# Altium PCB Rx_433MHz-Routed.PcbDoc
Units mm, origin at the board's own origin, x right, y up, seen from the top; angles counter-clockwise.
Board outline 100 x 50 mm, 4 copper layers (SIGNAL_1, SIGNAL_2, SIGNAL_3, SIGNAL_4), stack 1.58 mm thick; 51 components, 60 nets, 198 pads, 218 vias.
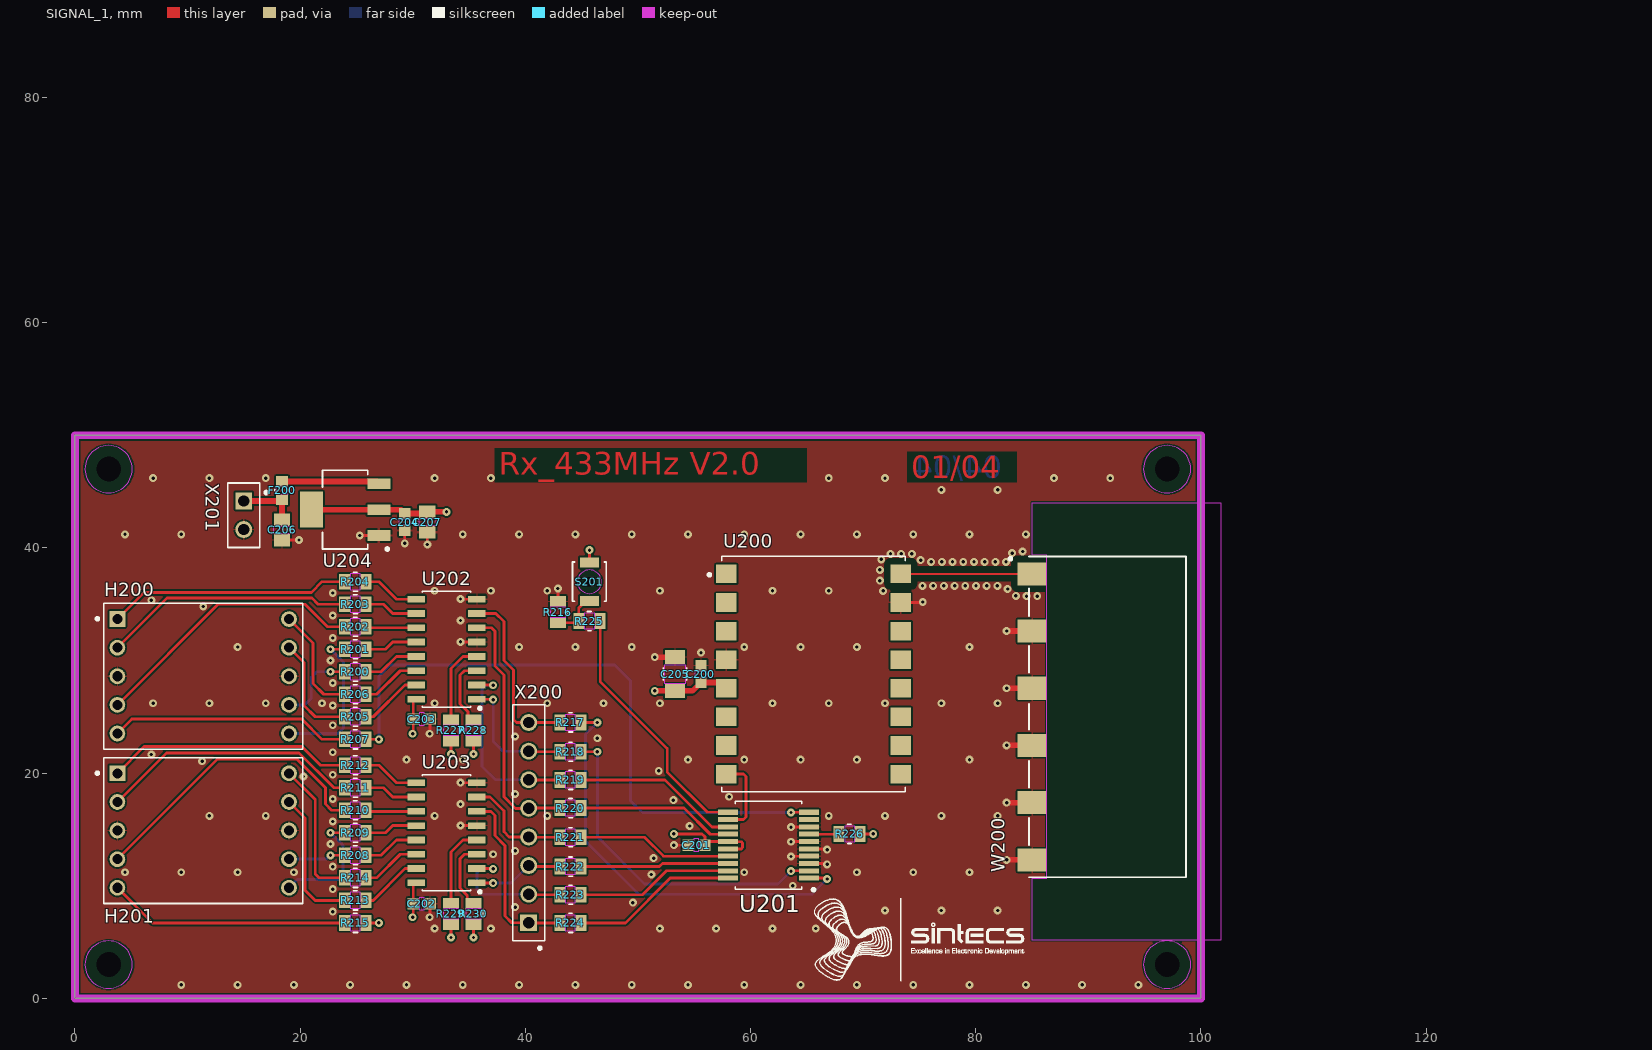
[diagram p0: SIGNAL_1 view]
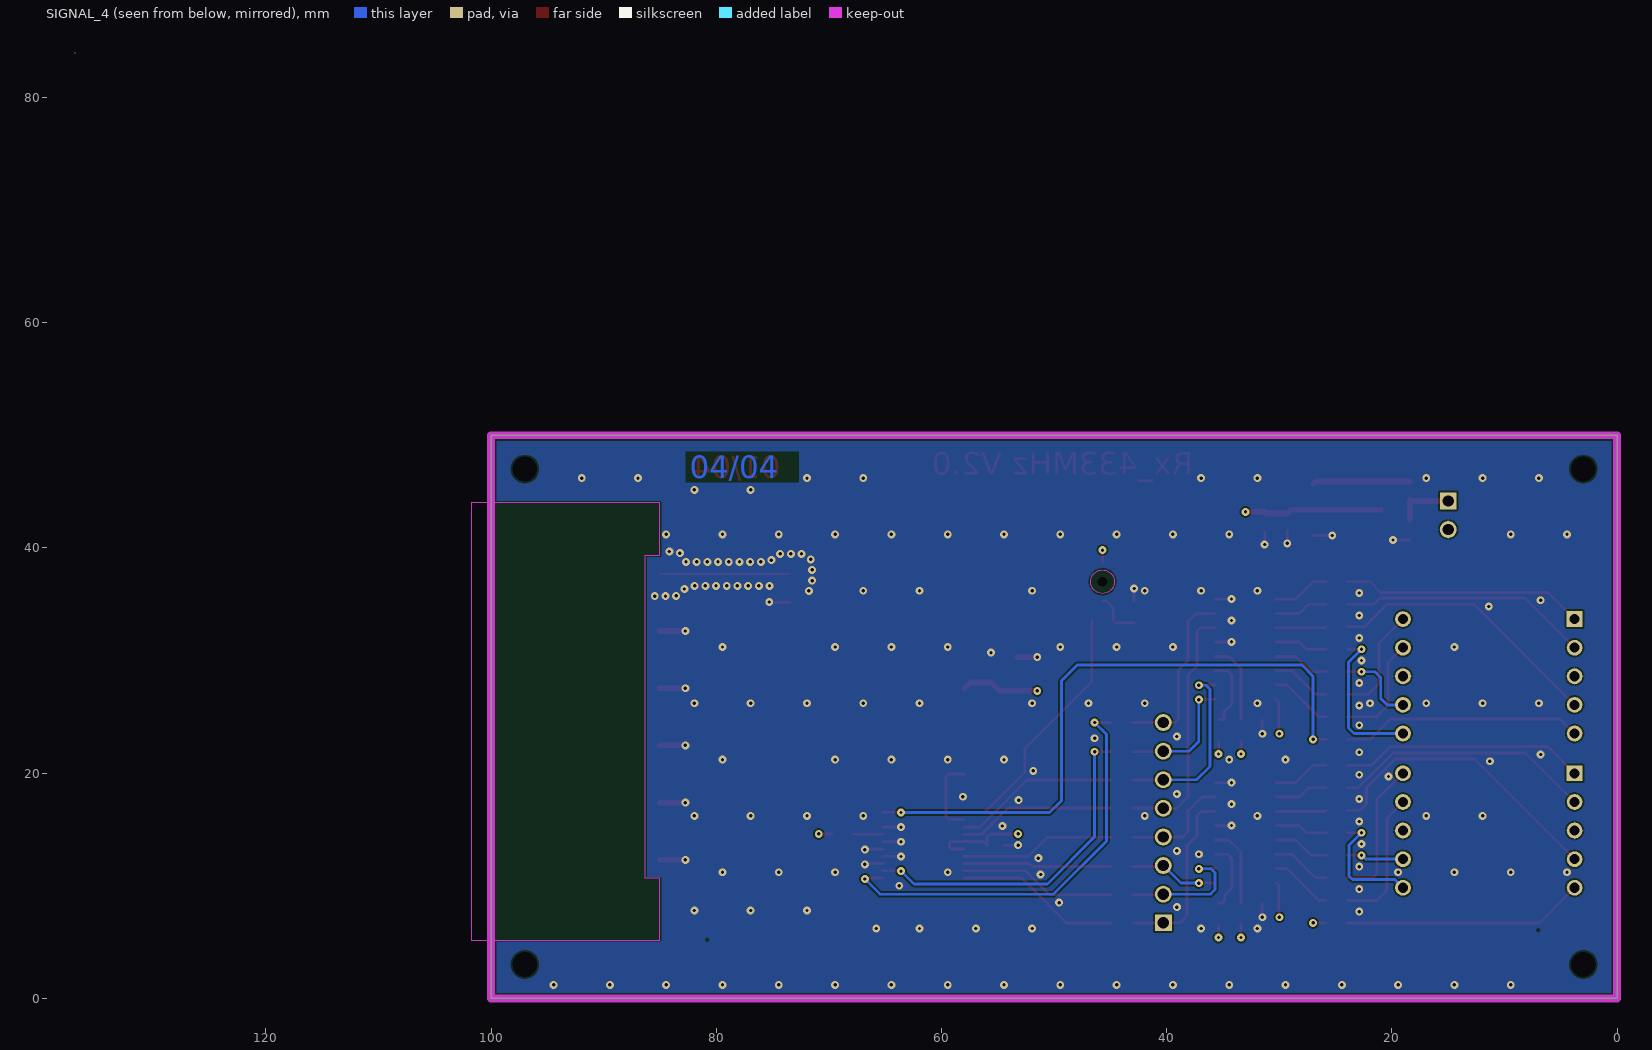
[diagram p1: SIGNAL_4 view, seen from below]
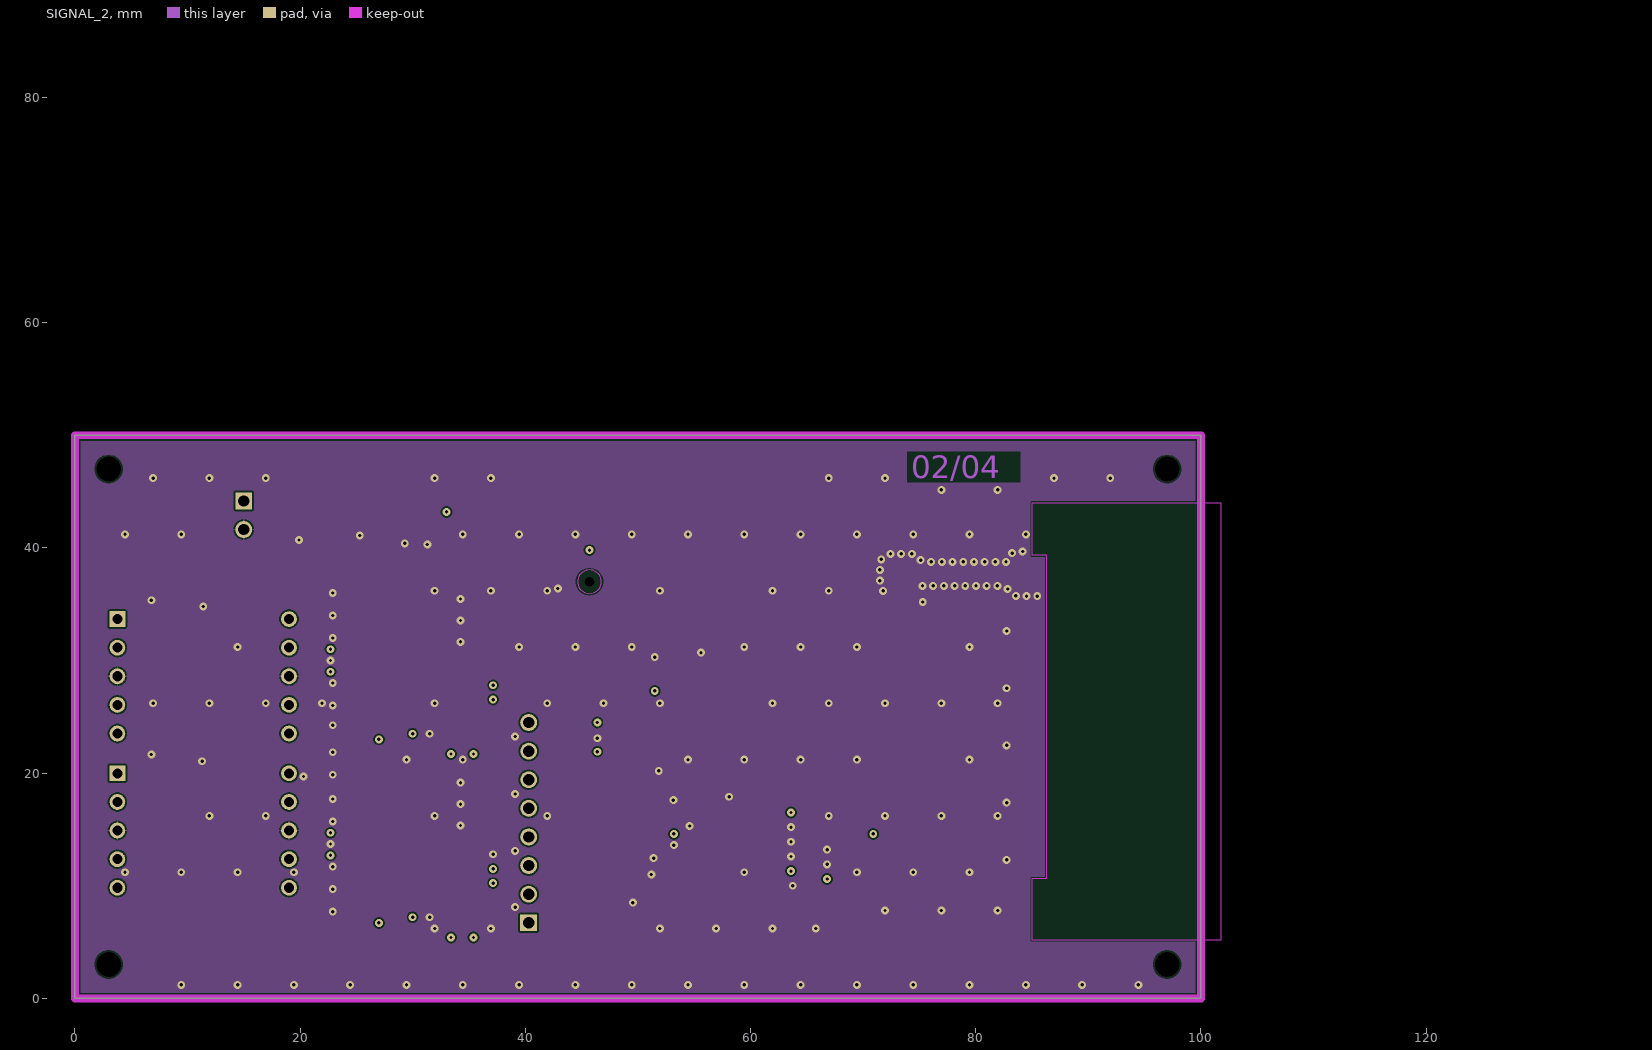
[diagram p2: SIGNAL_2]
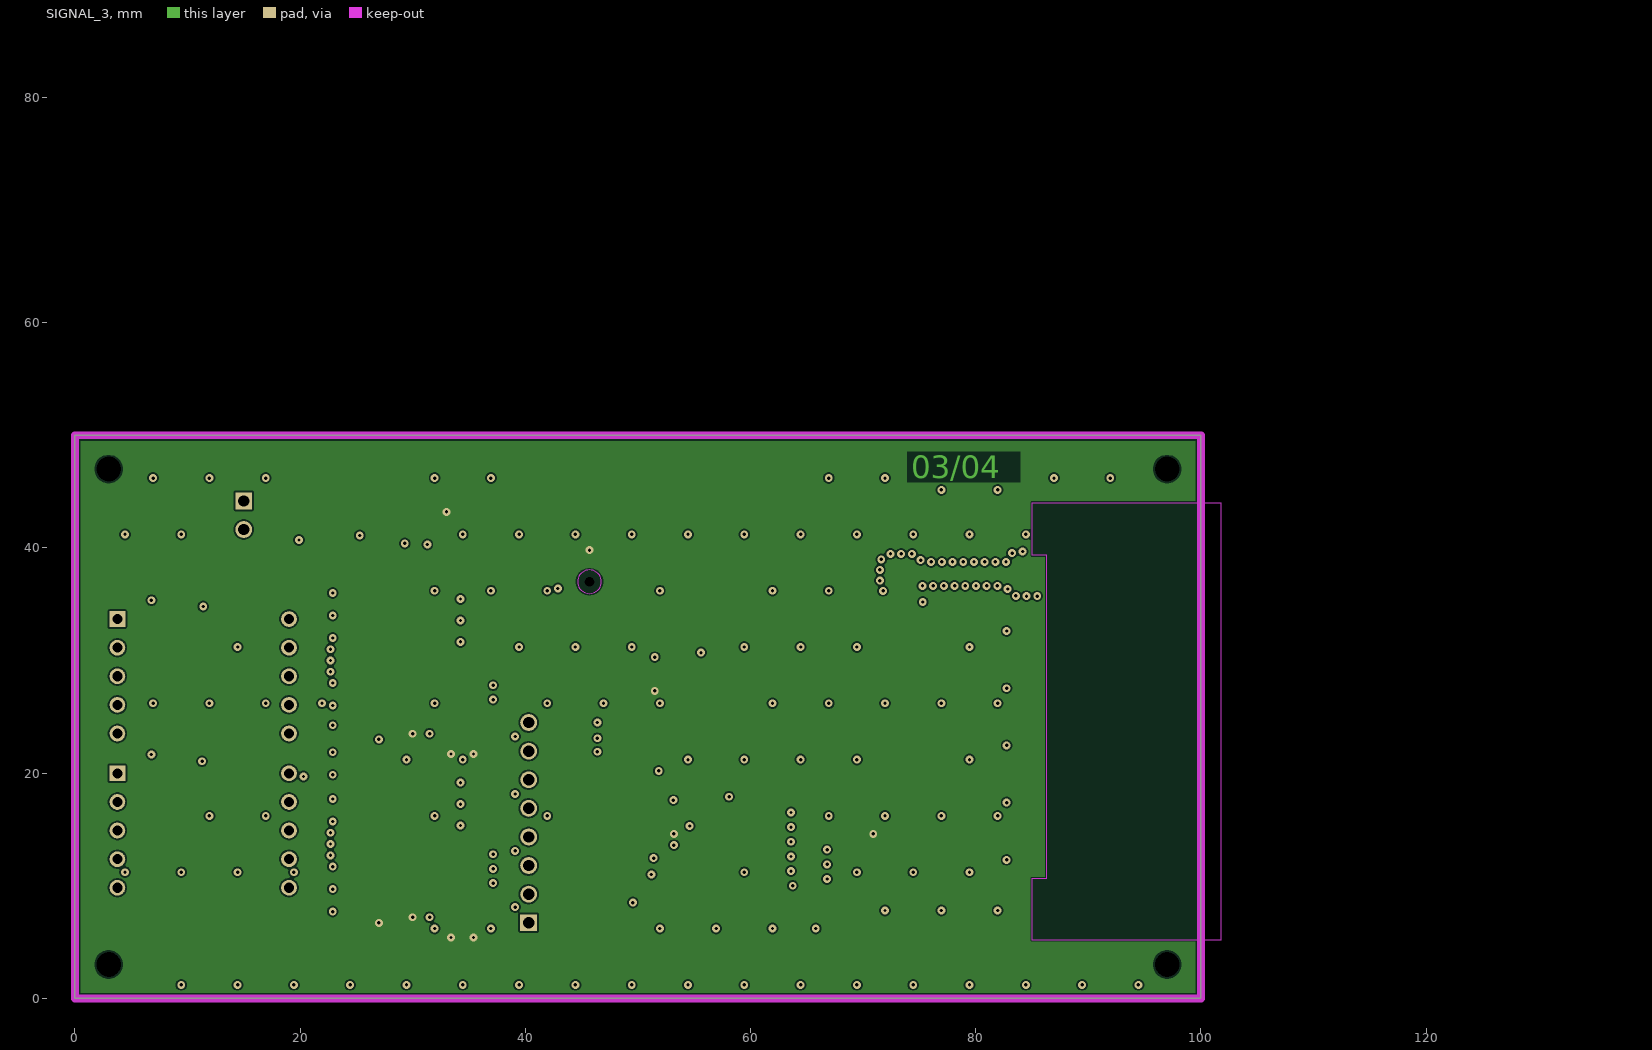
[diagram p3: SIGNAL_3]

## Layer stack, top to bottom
DIELECTRIC_1: solder mask 0.01, Dk 1
SIGNAL_1: signal copper 0.035
DIELECTRIC_3: prepreg 0.12, Dk 4.7
SIGNAL_2: signal copper 0.035
DIELECTRIC_5: prepreg 1.2, Dk 4.7
SIGNAL_3: signal copper 0.035
DIELECTRIC_7: prepreg 0.12, Dk 4.7
SIGNAL_4: signal copper 0.035
DIELECTRIC_9: solder mask 0.01, Dk 1

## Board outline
0,0 0,50 100,50 100,0

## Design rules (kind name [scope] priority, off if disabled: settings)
Clearance Clearance_50R [InNetClass('50R')] p1: gap=0.6 ignorepadtopadclearanceinfootprint=FALSE except(0.2: SMDPad-SMDPad)
Clearance [All] p2: gap=0.15 ignorepadtopadclearanceinfootprint=FALSE
ComponentClearance [All] p1: gap=0.1 collisioncheckmode=3 verticalgap=0.254 showdistances=FALSE
DiffPairsRouting [All] p1: maxlimit=0.254 minlimit=0.254 mostfreqgap=0.254 toplayer_minwidth=0.15 toplayer_maxwidth=0.3 toplayer_prefwidth=0.15 midlayer1_minwidth=0.15 midlayer1_maxwidth=0.3 midlayer1_prefwidth=0.15 midlayer2_minwidth=0.15 midlayer2_maxwidth=0.3 midlayer2_prefwidth=0.15 bottomlayer_minwidth=0.15 bottomlayer_maxwidth=0.3 bottomlayer_prefwidth=0.15 maxuncoupledlength=12.7
MinimumSolderMaskSliver [All] p1: minsoldermaskwidth=0.1
PolygonConnect [All] p1: thpad.connectstyle=Relief thpad.reliefconductorwidth=0.15 thpad.reliefentries=4 thpad.polygonreliefangle="90 Angle" thpad.airgapwidth=0.15 smdpad.connectstyle=Relief smdpad.reliefconductorwidth=0.15 smdpad.reliefentries=4 smdpad.polygonreliefangle="90 Angle" smdpad.airgapwidth=0.15 via.connectstyle=Direct via.reliefconductorwidth=0.127 via.reliefentries=2 via.polygonreliefangle="90 Angle" via.airgapwidth=0.152
RoutingVias [All] p1: holewidth=0.3 width=0.7 viastyle="Through Hole" minholewidth=0.3 minwidth=0.7 maxholewidth=0.3 maxwidth=0.7
SilkToSilkClearance [All] p1: silktosilkclearance=0.1
SolderMaskExpansion SolderMaskExpansion_Via [IsVia] p1: expansion=0.075 istentingtop=FALSE soldermaskfromhole=TRUE
SolderMaskExpansion [All] p2: expansion=0.1 istentingtop=FALSE
SupplyNets "Schematic Supply Nets_1" [InNet('3V3_RX')] p1: voltage=0.000
SupplyNets "Schematic Supply Nets" [InNet('GND_RX')] p2: voltage=0.000
UnRoutedNet [All] p1: checkbadconnections=TRUE
Width "Width for 50E_SE" [InNetClass('50R')] p1: maxlimit=0.2 minlimit=0.185 preferedwidth=0.2 toplayer_minwidth=0.2 bottomlayer_minwidth=0.2 impedanceprofiledriven=TRUE impedanceprofileid={877E34D1-77DC-4DEE-A0FB-207FE4FBDA97} impedanceprofilevalue=50.000000 minimp=50.000000 maximp=50.000000 favimp=50.000000
Width [All] p2: maxlimit=1 minlimit=0.15 preferedwidth=0.2
25 further rules are at their usual default settings.

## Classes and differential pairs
net class 50R: RF_RX
polygon class "\"(Inherited)\"": GND_RX_L02_P002

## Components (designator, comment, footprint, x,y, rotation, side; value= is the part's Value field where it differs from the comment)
C200 "C_0603_1608X90_GENERIC" CAPC1608X90N_0603_GENERIC 55.6,28.8 r90 top value=100nF
C201 "C_0603_1608X90_GENERIC" CAPC1608X90N_0603_GENERIC 55.2,13.6 r180 top value=100nF
C202 "C_0603_1608X90_GENERIC" CAPC1608X90N_0603_GENERIC 30.8,8.4 r0 top value=100nF
C203 "C_0603_1608X90_GENERIC" CAPC1608X90N_0603_GENERIC 30.8,24.8 r0 top value=100nF
C204 "C_0603_1608X90_GENERIC" CAPC1608X90N_0603_GENERIC 29.3,42.3 r270 top value=100nF
C205 "C_1206_3216X190_GENERIC" CAPC3216X190N_1206_GENERIC 53.3,28.8 r90 top value=10uF
C206 "08051C104KAZ2A" CAPC2013X140N_AVX 18.398,41.6 r270 top value=10uF
C207 "08051C104KAZ2A" CAPC2013X140N_AVX 31.3,42.3 r270 top value=10uF
F200 "0467XXXX" RESC1608X60N_0603_GENERIC 18.4,45.1 r90 top value=500mA
H200 "HDSP-5XXX" BROADCOM_HDSP-5XXX 11.4,28.6 r0 top
H201 "HDSP-5XXX" BROADCOM_HDSP-5XXX 11.4,14.9 r0 top
R200 "R_0805_2012X60_GENERIC" RESC2012X60N_0805_GENERIC 24.9,29.001 r180 top value=120R
R201 "R_0805_2012X60_GENERIC" RESC2012X60N_0805_GENERIC 24.9,31.001 r180 top value=120R
R202 "R_0805_2012X60_GENERIC" RESC2012X60N_0805_GENERIC 24.9,33.001 r180 top value=120R
R203 "R_0805_2012X60_GENERIC" RESC2012X60N_0805_GENERIC 24.9,35.001 r180 top value=120R
R204 "R_0805_2012X60_GENERIC" RESC2012X60N_0805_GENERIC 24.9,37.002 r180 top value=120R
R205 "R_0805_2012X60_GENERIC" RESC2012X60N_0805_GENERIC 24.9,25 r180 top value=120R
R206 "R_0805_2012X60_GENERIC" RESC2012X60N_0805_GENERIC 24.9,27 r180 top value=120R
R207 "R_0805_2012X60_GENERIC" RESC2012X60N_0805_GENERIC 24.9,23 r180 top value=120R
R208 "R_0805_2012X60_GENERIC" RESC2012X60N_0805_GENERIC 24.9,12.7 r180 top value=120R
R209 "R_0805_2012X60_GENERIC" RESC2012X60N_0805_GENERIC 24.9,14.7 r180 top value=120R
R210 "R_0805_2012X60_GENERIC" RESC2012X60N_0805_GENERIC 24.9,16.701 r180 top value=120R
R211 "R_0805_2012X60_GENERIC" RESC2012X60N_0805_GENERIC 24.9,18.701 r180 top value=120R
R212 "R_0805_2012X60_GENERIC" RESC2012X60N_0805_GENERIC 24.9,20.701 r180 top value=120R
R213 "R_0805_2012X60_GENERIC" RESC2012X60N_0805_GENERIC 24.9,8.7 r180 top value=120R
R214 "R_0805_2012X60_GENERIC" RESC2012X60N_0805_GENERIC 24.9,10.7 r180 top value=120R
R215 "R_0805_2012X60_GENERIC" RESC2012X60N_0805_GENERIC 24.9,6.7 r180 top value=120R
R216 "R_0805_2012X60_GENERIC" RESC2012X60N_0805_GENERIC 42.9,34.3 r270 top value=100K
R217 "R_0805_2012X60_GENERIC" RESC2012X60N_0805_GENERIC 44,24.5 r180 top value=1K
R218 "R_0805_2012X60_GENERIC" RESC2012X60N_0805_GENERIC 44,21.9 r180 top value=1K
R219 "R_0805_2012X60_GENERIC" RESC2012X60N_0805_GENERIC 44,19.4 r180 top value=1K
R220 "R_0805_2012X60_GENERIC" RESC2012X60N_0805_GENERIC 44,16.9 r180 top value=1K
R221 "R_0805_2012X60_GENERIC" RESC2012X60N_0805_GENERIC 44,14.3 r180 top value=1K
R222 "R_0805_2012X60_GENERIC" RESC2012X60N_0805_GENERIC 44,11.7 r180 top value=1K
R223 "R_0805_2012X60_GENERIC" RESC2012X60N_0805_GENERIC 44,9.2 r180 top value=1K
R224 "R_0805_2012X60_GENERIC" RESC2012X60N_0805_GENERIC 44,6.7 r180 top value=1K
R225 "R_0805_2012X60_GENERIC" RESC2012X60N_0805_GENERIC 45.7,33.5 r0 top value=1K
R226 "R_0805_2012X60_GENERIC" RESC2012X60N_0805_GENERIC 68.8,14.6 r0 top value=100K
R227 "R_0805_2012X60_GENERIC" RESC2012X60N_0805_GENERIC 33.4,23.8 r270 top value=100K
R228 "R_0805_2012X60_GENERIC" RESC2012X60N_0805_GENERIC 35.4,23.8 r270 top value=100K
R229 "R_0805_2012X60_GENERIC" RESC2012X60N_0805_GENERIC 33.4,7.5 r270 top value=100K
R230 "R_0805_2012X60_GENERIC" RESC2012X60N_0805_GENERIC 35.4,7.5 r270 top value=100K
S201 "B3U_1000P_B" OMRON_B3U_1000P_B 45.7,37 r270 top
U200 "RXM-433-LR" LINX_RXM-433-LR 65.6,28.8 r0 top
U201 "LICAL-DEC-MS001" SOP65P780X200-20N 61.6,13.6 r180 top
U202 "CD74HC4511M" SOIC127P600X175-16N 33,31 r180 top
U203 "CD74HC4511M" SOIC127P600X175-16N 33,14.7 r180 top
U204 "LM1117MPX" SOT230P700X180-4N 25.498,43.4 r180 top
W200 "ANT-433-SP" LINX_ANT-433-SP 85,25 r270 top
X200 "M20_9770842" HARWIN_M20_9770842 40.3,15.6 r90 top
X201 "M20_9770242" HARWIN_M20_9770242 15,42.9 r270 top

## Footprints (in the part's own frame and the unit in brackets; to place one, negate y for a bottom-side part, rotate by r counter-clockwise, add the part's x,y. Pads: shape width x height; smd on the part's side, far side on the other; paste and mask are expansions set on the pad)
BROADCOM_HDSP-5XXX [mm]
  rrect1% 1.4x1.4 hole 0.9 paste-2539.97 mask-0.713: 1(-7.62,5.08)
  round 1.4 hole 0.9 paste-2539.97 mask-0.713: 2(-7.62,2.54) 3(-7.62,0) 4(-7.62,-2.54) 5(-7.62,-5.08) 6(7.62,-5.08) 7(7.62,-2.54) 8(7.62,0) 9(7.62,2.54) 10(7.62,5.08)
  silkscreen extent -9.53,-6.47 8.83,6.48, body extent -8.92,-6.57 8.93,6.58, height 8.25
CAPC1608X90N_0603_GENERIC [mm]
  rrect1% 1x1 smd paste-2539.97 mask-0.513: 1(-0.75,0) 2(0.75,0)
  SIGNAL_1 keep-out region: -0.22,-0.55 0.22,-0.55 0.22,0.55 -0.22,0.55
  body extent -1.5,-0.75 1.5,0.75, height 0.9
CAPC2013X140N_AVX [mm]
  rrect1% 1.15x1.45 smd paste-2539.97 mask-0.738: 1(-0.9,0) 2(0.9,0)
  SIGNAL_1 keep-out region: -0.28,-0.78 0.28,-0.78 0.28,0.78 -0.28,0.78
  body extent -1.73,-1.05 1.73,1.05, height 1.4
CAPC3216X190N_1206_GENERIC [mm]
  rrect1% 1.25x1.8 smd paste-2539.97 mask-0.913: 1(-1.5,0) 2(1.5,0)
  SIGNAL_1 keep-out region: -0.8,-0.95 0.8,-0.95 0.8,0.95 -0.8,0.95
  silkscreen extent -0.55,-1.05 0.55,1.05, body extent -2.4,-1.15 2.4,1.15, height 1.9
HARWIN_M20_9770242 [mm]
  rrect1% 1.5x1.5 hole 1 paste-2539.97 mask-0.763: 1(-1.27,0)
  round 1.5 hole 1 paste-2539.97 mask-0.763: 2(1.27,0)
  silkscreen extent -2.87,-1.42 2.86,2.12, body extent -2.97,-1.52 2.96,1.52, height 8.38
HARWIN_M20_9770842 [mm]
  rrect1% 1.5x1.5 hole 1 paste-2539.97 mask-0.763: 1(-8.89,0)
  round 1.5 hole 1 paste-2539.97 mask-0.763: 2(-6.35,0) 3(-3.81,0) 4(-1.27,0) 5(1.27,0) 6(3.81,0) 7(6.35,0) 8(8.89,0)
  silkscreen extent -11.26,-1.42 10.48,1.42, body extent -10.59,-1.52 10.59,1.52, height 8.34
LINX_ANT-433-SP [mm]
  rrect1% 2.05x2.55 smd paste-2539.97 mask-1.288: 1(-12.7,0) 2(-7.62,0) 3(-2.54,0) 4(2.54,0) 5(7.62,0) 6(12.7,0)
  SIGNAL_1 keep-out region: 14.35,0 14.35,1.3 -14.35,1.3 -14.35,0 -19.03,0 -19.03,16.78 19.83,16.78 19.83,0
  SIGNAL_2 keep-out region: 14.35,0 14.35,1.3 -14.35,1.3 -14.35,0 -19.03,0 -19.03,16.78 19.83,16.78 19.83,0
  SIGNAL_3 keep-out region: 14.35,0 14.35,1.3 -14.35,1.3 -14.35,0 -19.03,0 -19.03,16.78 19.83,16.78 19.83,0
  SIGNAL_4 keep-out region: 14.35,0 14.35,1.3 -14.35,1.3 -14.35,0 -19.03,0 -19.03,16.78 19.83,16.78 19.83,0
  silkscreen extent -14.24,-2.04 14.24,13.67, body extent -14.34,-1.55 14.34,13.77, height 1.5
LINX_RXM-433-LR [mm]
  rrect1% 1.8x1.65 smd paste-2539.97 mask-0.913: 1(-7.747,8.89) 2(-7.747,6.35) 3(-7.747,3.81) 4(-7.747,1.27) 5(-7.747,-1.27) 6(-7.747,-3.81) 7(-7.747,-6.35) 8(-7.747,-8.89) 9(7.747,-8.89) 10(7.747,-6.35) 11(7.747,-3.81) 12(7.747,-1.27) 13(7.747,1.27) 14(7.747,3.81) 15(7.747,6.35) 16(7.747,8.89)
  silkscreen extent -9.38,-10.45 8.15,10.45, body extent -8.9,-10.65 8.9,10.65, height 3.12
OMRON_B3U_1000P_B [mm]
  rrect1% 0.9x1.7 smd paste-2539.97 mask-0.863: 1(-1.7,0) 2(1.7,0)
  round 0 hole 0.85 unplated paste-2539.97 mask+0.925: ""(0,0)
  SIGNAL_1 keep-out region: 1.05,0 0.97,0.402 0.742,0.742 0.402,0.97 0,1.05 0,1.05 -0.402,0.97 -0.742,0.742 -0.97,0.402 -1.05,0 -1.05,0 -0.97,-0.402 -0.742,-0.742 -0.402,-0.97 0,-1.05 0,-1.05 0.402,-0.97 0.742,-0.742 0.97,-0.402 1.05,0
  SIGNAL_2 keep-out region: 1.05,0 0.97,0.402 0.742,0.742 0.402,0.97 0,1.05 0,1.05 -0.402,0.97 -0.742,0.742 -0.97,0.402 -1.05,0 -1.05,0 -0.97,-0.402 -0.742,-0.742 -0.402,-0.97 0,-1.05 0,-1.05 0.402,-0.97 0.742,-0.742 0.97,-0.402 1.05,0
  SIGNAL_3 keep-out region: 1.05,0 0.97,0.402 0.742,0.742 0.402,0.97 0,1.05 0,1.05 -0.402,0.97 -0.742,0.742 -0.97,0.402 -1.05,0 -1.05,0 -0.97,-0.402 -0.742,-0.742 -0.402,-0.97 0,-1.05 0,-1.05 0.402,-0.97 0.742,-0.742 0.97,-0.402 1.05,0
  SIGNAL_4 keep-out region: 1.05,0 0.97,0.402 0.742,0.742 0.402,0.97 0,1.05 0,1.05 -0.402,0.97 -0.742,0.742 -0.97,0.402 -1.05,0 -1.05,0 -0.97,-0.402 -0.742,-0.742 -0.402,-0.97 0,-1.05 0,-1.05 0.402,-0.97 0.742,-0.742 0.97,-0.402 1.05,0
  silkscreen extent -1.75,-1.5 1.75,1.5, body extent -2.4,-1.6 2.4,1.6, height 1.75
RESC1608X60N_0603_GENERIC [mm]
  rrect1% 0.95x1.05 smd paste-2539.97 mask-0.538: 1(-0.8,0) 2(0.8,0)
  SIGNAL_1 keep-out region: -0.3,-0.55 0.3,-0.55 0.3,0.55 -0.3,0.55
  silkscreen extent -0.08,-0.65 0.08,0.65, body extent -1.55,-0.8 1.55,0.8, height 0.6
RESC2012X60N_0805_GENERIC [mm]
  rrect1% 0.95x1.4 smd paste-2539.97 mask-0.713: 1(-0.95,0) 2(0.95,0)
  SIGNAL_1 keep-out region: -0.45,-0.7 0.45,-0.7 0.45,0.7 -0.45,0.7
  silkscreen extent -0.2,-0.85 0.15,0.85, body extent -1.7,-0.95 1.7,0.95, height 0.6
SOIC127P600X175-16N [mm]
  rrect1% 1.55x0.6 smd paste-2539.97 mask-0.788: 1(-2.7,4.445) 2(-2.7,3.175) 3(-2.7,1.905) 4(-2.7,0.635) 5(-2.7,-0.635) 6(-2.7,-1.905) 7(-2.7,-3.175) 8(-2.7,-4.445) 9(2.7,-4.445) 10(2.7,-3.175) 11(2.7,-1.905) 12(2.7,-0.635) 13(2.7,0.635) 14(2.7,1.905) 15(2.7,3.175) 16(2.7,4.445)
  silkscreen extent -3.1,-5.16 2.15,5.38, body extent -3.73,-5.25 3.73,5.25, height 1.75
SOP65P780X200-20N [mm]
  rrect1% 1.75x0.45 smd paste-2539.97 mask-0.888: 1(-3.6,2.925) 2(-3.6,2.275) 3(-3.6,1.625) 4(-3.6,0.975) 5(-3.6,0.325) 6(-3.6,-0.325) 7(-3.6,-0.975) 8(-3.6,-1.625) 9(-3.6,-2.275) 10(-3.6,-2.925) 11(3.6,-2.925) 12(3.6,-2.275) 13(3.6,-1.625) 14(3.6,-0.975) 15(3.6,-0.325) 16(3.6,0.325) 17(3.6,0.975) 18(3.6,1.625) 19(3.6,2.275) 20(3.6,2.925)
  silkscreen extent -4.12,-3.9 2.95,4.08, body extent -4.75,-4 4.75,4, height 2
SOT230P700X180-4N [mm]
  rrect1% 2.05x0.95 smd paste-2539.97 mask-1.038: 1(-1.5,2.3) 2(-1.5,0) 3(-1.5,-2.3)
  rrect1% 2.05x3.2 smd paste-2539.97 mask-1.613: 4(4.5,0)
  silkscreen extent -2.37,-3.5 3.5,3.62, body extent -2.8,-3.6 5.8,3.6, height 1.8

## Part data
C200 C201 C202 C203 C204: "100nF 25V 10%", Capacitance=100000, Dielectric=X7R, Manufacturer=MURATA, MPN=GRM188R71E104KA01D, Package=0603, Part Name="Ceramic chip capacitor 0603-1608x90, generic", Tolerance=10, Voltage=25V
C205: "10uF 25V 10%", Capacitance=10000000, Dielectric=X7R, Manufacturer=AVX, Max Temp=+125, Min Temp=-55, MPN=12063C106KAT2A, Package=1206, Part Name="Cheramic chip capacitor 1206-3216x190, generic", Tolerance=10, Voltage=25V
C206 C207: "10uF 25V 10%", Capacitance=10000000, Dielectric=X5R, Manufacturer=AVX, MPN=08053D106KAT2A, Package=0805, Part Name="0805 chip 100nF 10% 100V X7R", Tolerance=10, Voltage=25V
F200: "Thin film 0603 fuse very fast acting", Current=0.5, Manufacturer=LITTELFUSE, Max Temp=+90, Min Temp=-55, MPN=0467.500NRHF, Package=0603, Part Name="Thin film 0603 very fast acting", Voltage=32V
H200 H201: "7 Segment Display Module Red, 1,85V, 20mA. THT", Color=Red, Manufacturer=BROADCOM, Max Temp=85, Min Temp=-25, MPN=HDSP-515A, Part Name="Single Digit LED Numeric Display, Blue color"
R200 R201 R202 R203 R204 R205 R206 R207 R208 R209 R210 R211 R212 R213 R214 R215: "0.125W 5% 120R 50V", Manufacturer=YAGEO, MPN=RC0805JR-07120RL, Package=0805, Part Name="resistor_0805-2012x60 generic", Tolerance=5%
R216 R226 R227 R228 R229 R230: "0.125W 5% 100K 50V", Manufacturer=YAGEO, MPN=RC0805JR-07100KL, Package=0805, Part Name="resistor_0805-2012x60 generic", Tolerance=5%
R217 R218 R219 R220 R221 R222 R223 R224 R225: "Resistor_1K_1%_0805", Manufacturer=MULTICOMP, MPN=MCPWR05FTEW1001, Package=0805, Part Name="resistor_0805-2012x60 generic", Tolerance=1%
S201: "Ultra-small Tactile Switch", Manufacturer=OMRON, Max Temp=0, MPN=B3U-1000P-B
U200: "LR Series Receiver, Low Voltage, Low Power", Manufacturer="Linx Technologies", Max Temp=70, Min Temp=-40, Package=custom
U201: "MS Series Remote Controler Decoder, Low Voltage, Low Power", Manufacturer="LINX TECHNOLOGIES", Max Temp=85, Min Temp=-40, MPN=LICAL-DEC-MS001-T, Package=SOP-20
U202 U203: "Leddriver BCD to 7 segment 1 Digit", Manufacturer="TEXAS INSTRUMENTS", Max Temp=125, Min Temp=-55, Package=SOIC-16N
U204: "3.3V/1A fixed regulator", Manufacturer=ON-SEMI, MPN=NCP1117LPST33T3G, Package=SOT, Part Name="800mA Low-Dropout Linear Regulator, SOT223"
W200: "433MHz 50 Ohm Antenna module", Manufacturer="Linx Technologies", Max Temp=130, Min Temp=-40, Package=custom
X200: "1x8 pin 2.54 mm pitch vertical header", Manufacturer=HARWIN, MPN=M20-9770842, Package=header, Part Name=STD_HEADER_1x8_2.54_THT
X201: "1x2 pin 2.54 mm pitch vertical header", Manufacturer=HARWIN, MPN=M20-9770242, Package=header, Part Name=STD_HEADER_1x2_2.54_THT

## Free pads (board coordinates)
  round 0 hole 2.2 unplated paste-2539.97 mask+1.6: ""(3,3) ""(3,47) ""(97,3) ""(97,47)
  round 0.025 smd far side paste-2539.97 mask-127: ""(7,6.05) ""(80.8,5.2) ""(136.95,83.95)

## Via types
v1: diameter 0.7, hole 0.3, SIGNAL_1 to SIGNAL_4, 218 vias

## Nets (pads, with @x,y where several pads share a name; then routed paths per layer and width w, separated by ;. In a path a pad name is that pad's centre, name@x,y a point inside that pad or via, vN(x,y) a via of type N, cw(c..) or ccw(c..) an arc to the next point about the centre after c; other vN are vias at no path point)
3V3_RX: C200.1 C201.1 C202.1 C203.1 C204.1 C205.1 C207.1 R215.1 R226.2 R227.2 R228.2 R229.2 R230.2 S201.1 U200.5 U201.15 U201.16 U202.16 U203.16 U204.2 U204.4 | length 42.4
  SIGNAL_1 w0.25: R215.1 v1(27,6.7) ; v1(30,7.2) 30.05,7.25 C202.1 30.05,10.005 U203.16 ; v1(30,23.5) 30.05,23.55 30.05,26.305 U202.16 ; v1(33.4,5.4) R229.2 ; v1(33.4,21.7) R227.2 ; v1(35.4,5.4) R230.2 ; v1(35.4,21.7) R228.2 ; S201.1 v1(45.7,39.8) ; v1(53.2,14.6) 55.7,14.6 55.95,14.35 C201.1 56.275,13.925 U201.15 58.025,13.9 59.2,13.9 59.3,13.8 59.3,13.4 59.175,13.275 U201.16 ; R226.2 v1(70.9,14.6)
  SIGNAL_1 w0.5: U204.4 U204.2 28.95,43.4 C204.1 31.15,43.05 C207.1 v1(33,43.2) ; v1(51.5,27.3) C205.1 54.85,27.3 C200.1 57.433,28.05 U200.5@57.953,27.53
DEC_MODE_IND: R207.1 U201.10 | length 57
  SIGNAL_1 w0.25: R207.1 v1(27,23) ; v1(63.6,16.5) 63.625,16.525 U201.10
  SIGNAL_4 w0.25: v1(27,23) 27,28.6 28,29.6 47.95,29.6 49.35,28.2 49.35,17.55 50.4,16.5 v1(63.6,16.5)
GND_RX: C200.2 C201.2 C202.2 C203.2 C204.2 C205.2 C206.2 C207.2 H200.3 H200.8 H201.3 H201.8 R216.1 U200.4 U200.15 U201.3 U201.4 U201.5 U201.6 U201.8 U202.5 U202.8 U203.5 U203.8 U204.1 W200.2 W200.3 W200.4 W200.5 W200.6 X201.2 | length 39.1
  SIGNAL_1 w0.25: C206.2 v1(19.9,40.7) ; v1(25.3,41.1) U204.1 ; v1(29.3,40.4) C204.2 ; v1(31.3,40.3) C207.2 ; v1(31.5,7.2) 31.55,7.25 C202.2 ; v1(31.5,23.5) 31.55,23.55 C203.2@31.55,24.7 ; v1(34.25,15.35) 34.265,15.335 U203.5 ; v1(34.25,19.16) 34.265,19.145 U203.8 ; v1(34.25,31.65) 34.265,31.635 U202.5 ; v1(34.25,35.46) 34.265,35.445 U202.8 ; R216.1 v1(42.9,36.4) ; v1(53.2,13.6) C201.2 ; v1(63.6,12.6) 63.625,12.625 U201.4 ; v1(63.6,13.9) 63.625,13.925 U201.6 ; v1(63.6,15.2) 63.625,15.225 U201.8 ; U201.3 66.725,11.975 v1(66.8,11.9) ; U201.5 66.725,13.275 v1(66.8,13.2) ; U200.15@73.447,35.15 75.25,35.15 v1(75.3,35.2)
  SIGNAL_1 w0.5: v1(51.5,30.3) C205.2 ; v1(82.75,12.3) W200.6 ; v1(82.75,17.38) W200.5 ; v1(82.75,22.46) W200.4 ; v1(82.75,27.54) W200.3 ; v1(82.75,32.62) W200.2
  other v1: 9.45,1.2 14.45,1.2 19.45,1.2 24.45,1.2 29.45,1.2 34.45,1.2 39.45,1.2 44.45,1.2 49.45,1.2 54.45,1.2 59.45,1.2 64.45,1.2 69.45,1.2 74.45,1.2 79.45,1.2 84.45,1.2 89.45,1.2 94.45,1.2 31.95,6.2 36.95,6.2 51.95,6.2 56.95,6.2 61.95,6.2 65.8,6.2 22.9,7.7 71.95,7.8 76.95,7.8 81.95,7.8 39.1,8.1 49.55,8.5 22.9,9.7 63.75,10 51.2,11 4.45,11.2 9.45,11.2 14.45,11.2 19.45,11.2 59.45,11.2 69.45,11.2 74.45,11.2 79.45,11.2 22.9,11.7 51.4,12.45 37.15,12.8 39.1,13.1 22.7,13.7 54.6,15.3 22.9,15.7 11.95,16.2 16.95,16.2 31.95,16.2 41.95,16.2 66.95,16.2 71.95,16.2 76.95,16.2 81.95,16.2 34.25,17.25 53.15,17.6 22.9,17.7 58.1,17.9 39.1,18.15 20.3,19.7 22.9,19.85 51.85,20.2 11.3,21.05 29.45,21.2 34.45,21.2 54.45,21.2 59.45,21.2 64.45,21.2 69.45,21.2 79.45,21.2 6.8,21.65 22.9,21.85 46.4,23.1 39.1,23.25 22.9,24.25 22.9,26 6.95,26.2 11.95,26.2 16.95,26.2 21.95,26.2 31.95,26.2 41.95,26.2 46.95,26.2 51.95,26.2 61.95,26.2 66.95,26.2 71.95,26.2 76.95,26.2 81.95,26.2 22.9,28 22.7,30 55.6,30.7 14.45,31.2 39.45,31.2 44.45,31.2 49.45,31.2 59.45,31.2 64.45,31.2 69.45,31.2 79.45,31.2 22.9,32 34.25,33.55 22.9,34 11.4,34.8 6.8,35.35 84.511,35.716 85.461,35.716 83.561,35.737 22.9,36 31.95,36.2 36.95,36.2 41.95,36.2 51.95,36.2 61.95,36.2 66.95,36.2 71.777,36.188 82.832,36.346 75.273,36.624 76.223,36.624 77.173,36.624 78.123,36.624 79.073,36.624 80.023,36.624 80.973,36.624 81.923,36.624 71.488,37.093 71.488,38.043 76.044,38.756 76.994,38.756 77.944,38.756 78.894,38.756 79.844,38.756 80.794,38.756 81.744,38.756 82.694,38.756 75.108,38.918 71.616,38.985 72.432,39.471 73.382,39.474 74.332,39.466 83.234,39.538 84.172,39.684 4.45,41.2 9.45,41.2 34.45,41.2 39.45,41.2 44.45,41.2 49.45,41.2 54.45,41.2 59.45,41.2 64.45,41.2 69.45,41.2 74.45,41.2 79.45,41.2 84.45,41.2 76.95,45.15 81.95,45.15 6.95,46.2 11.95,46.2 16.95,46.2 31.95,46.2 36.95,46.2 66.95,46.2 71.95,46.2 86.95,46.2 91.95,46.2
NetC206_1: C206.1 F200.1 X201.1 | length 5.3
  SIGNAL_1 w0.5: X201.1 18.27,44.17 F200.1 18.4,42.502 C206.1
NetF200_2: F200.2 U204.3 | length 8.7
  SIGNAL_1 w0.5: F200.2 26.798,45.9 U204.3
NetH200_1: H200.1 R204.2 | length 21.5
  SIGNAL_1 w0.25: H200.1 6.15,36.05 21,36.05 21.952,37.002 R204.2
NetH200_2: H200.2 R203.2 | length 22.2
  SIGNAL_1 w0.25: H200.2 8.19,35.55 21.05,35.55 21.599,35.001 R203.2
NetH200_4: H200.4 R202.2 | length 24.7
  SIGNAL_1 w0.25: H200.4 12.72,35 20.45,35 22.449,33.001 R202.2
NetH200_5: H200.5 R207.2 | length 21.4
  SIGNAL_1 w0.25: H200.5 5.06,24.8 20.15,24.8 21.95,23 R207.2
NetH200_6: H200.6 R201.2 | length 13.8
  SIGNAL_1 w0.25: v1(22.7,31) R201.2
  SIGNAL_4 w0.25: H200.6 23.37,23.52 23.85,24 23.85,29.85 v1(22.7,31)
NetH200_7: H200.7 R200.2 | length 7.2
  SIGNAL_1 w0.25: v1@22.701,29.001 R200.2
  SIGNAL_4 w0.25: H200.7 20.417,26.06 21,26.643 21,28.5 21.5,29 v1(22.7,29)
NetH200_9: H200.9 R205.2 | length 9.7
  SIGNAL_1 w0.25: H200.9 20.35,29.81 20.35,26 21.35,25 R205.2
NetH200_10: H200.10 R206.2 | length 9.8
  SIGNAL_1 w0.25: H200.10 21.15,31.55 21.15,27.95 22.1,27 R206.2
NetH201_1: H201.1 R212.2 | length 21.8
  SIGNAL_1 w0.25: H201.1 6.15,22.35 20.15,22.35 21.799,20.701 R212.2
NetH201_2: H201.2 R211.2 | length 23.3
  SIGNAL_1 w0.25: H201.2 8.14,21.8 19.9,21.8 22.999,18.701 R211.2
NetH201_4: H201.4 R210.2 | length 26.6
  SIGNAL_1 w0.25: H201.4 12.67,21.25 19.7,21.25 22.25,18.7 22.25,17.25 22.799,16.701 R210.2
NetH201_5: H201.5 R215.2 | length 21.5
  SIGNAL_1 w0.25: H201.5 6.9,6.7 R215.2
NetH201_6: H201.6 R209.2 | length 10.8
  SIGNAL_1 w0.25: v1@22.701,14.7 R209.2
  SIGNAL_4 w0.25: H201.6 19.75,10.55 23.5,10.55 23.8,10.85 23.8,13.599 v1(22.7,14.699)
NetH201_7: H201.7 R208.2 | length 5.1
  SIGNAL_1 w0.25: v1(22.7,12.699) R208.2
  SIGNAL_4 w0.25: H201.7 22.361,12.36 v1(22.7,12.699)
NetH201_9: H201.9 R213.2 | length 12.3
  SIGNAL_1 w0.25: H201.9 20.45,16.01 20.45,9.6 21.35,8.7 R213.2
NetH201_10: H201.10 R214.2 | length 12.6
  SIGNAL_1 w0.25: H201.10 21.35,17.65 21.35,11.05 21.7,10.7 R214.2
NetR200_1: R200.1 U202.13 | length 5
  SIGNAL_1 w0.25: R200.1 27.201,29.001 28.565,30.365 U202.13
NetR201_1: R201.1 U202.12 | length 4.7
  SIGNAL_1 w0.25: R201.1 27.6,31 28.235,31.635 U202.12
NetR202_1: R202.1 U202.11 | length 4.5
  SIGNAL_1 w0.25: R202.1 25.946,32.905 U202.11
NetR203_1: R203.1 U202.10 | length 4.8
  SIGNAL_1 w0.25: R203.1 25.851,35 27.4,35 28.225,34.175 U202.10
NetR204_1: R204.1 U202.9 | length 5.1
  SIGNAL_1 w0.25: R204.1 25.852,37 27,37 28.555,35.445 U202.9
NetR205_1: R205.1 U202.15 | length 5.6
  SIGNAL_1 w0.25: R205.1 26.5,25 29.325,27.825 U202.15
NetR206_1: R206.1 U202.14 | length 5.3
  SIGNAL_1 w0.25: R206.1 26.8,27 28.895,29.095 U202.14
NetR208_1: R208.1 U203.13 | length 5
  SIGNAL_1 w0.25: R208.1 27.201,12.701 28.565,14.065 U203.13
NetR209_1: R209.1 U203.12 | length 4.7
  SIGNAL_1 w0.25: R209.1@25.851,14.7 27.6,14.7 28.235,15.335 U203.12
NetR210_1: R210.1 U203.11 | length 4.5
  SIGNAL_1 w0.25: R210.1 25.946,16.605 U203.11
NetR211_1: R211.1 U203.10 | length 4.8
  SIGNAL_1 w0.25: R211.1 25.851,18.7 27.4,18.7 28.225,17.875 U203.10
NetR212_1: R212.1 U203.9 | length 5.1
  SIGNAL_1 w0.25: R212.1 25.852,20.7 27,20.7 28.555,19.145 U203.9
NetR213_1: R213.1 U203.15 | length 5.6
  SIGNAL_1 w0.25: R213.1 26.5,8.7 29.325,11.525 U203.15
NetR214_1: R214.1 U203.14 | length 5.3
  SIGNAL_1 w0.25: R214.1 26.8,10.7 28.895,12.795 U203.14
NetR216_2: R216.2 R225.1 S201.2 | length 4.3
  SIGNAL_1 w0.25: R216.2 44.6,33.35 R225.1 44.75,34.65 45.4,35.3 S201.2
NetR217_1: R217.1 U201.1 | length 38
  SIGNAL_1 w0.25: R217.1 v1(46.4,24.5) ; U201.1 66.725,10.675 v1(66.8,10.6)
  SIGNAL_4 w0.25: v1(46.4,24.5) 45.35,23.45 45.35,13.95 50.05,9.25 65.45,9.25 v1(66.8,10.6)
NetR217_2: R217.2 U202.7 X200.8 | length 16
  SIGNAL_1 w0.25: U202.7 37.375,34.175 38.1,33.45 38.1,30 38.95,29.15 38.95,24.75 39.21,24.49 X200.8 40.31,24.5 R217.2
NetR218_1: R218.1 U201.2 | length 30
  SIGNAL_1 w0.25: R218.1 v1(46.4,21.9) ; v1(63.6,11.3) 63.625,11.325 U201.2
  SIGNAL_4 w0.25: v1(46.4,21.9) 46.4,14.35 50.6,10.15 62.45,10.15 v1(63.6,11.3)
NetR218_2: R218.2 U202.1 X200.7 | length 11.5
  SIGNAL_1 w0.25: U202.1 37.125,26.555 v1(37.15,26.53) ; X200.7 40.35,21.9 R218.2
  SIGNAL_4 w0.25: v1(37.15,26.53) 37.15,22.8 38,21.95 X200.7
NetR219_1: R219.1 U201.13 | length 14.8
  SIGNAL_1 w0.25: R219.1 52.4,19.4 56.575,15.225 U201.13
NetR219_2: R219.2 U202.2 X200.6 | length 16.9
  SIGNAL_1 w0.25: U202.2 37.125,27.825 v1(37.15,27.8) ; X200.6 40.31,19.4 R219.2
  SIGNAL_4 w0.25: v1(37.15,27.8) 36.5,27.8 36.15,27.45 36.15,20.6 37.34,19.41 X200.6
NetR220_1: R220.1 U201.14 | length 14
  SIGNAL_1 w0.25: R220.1 54.1,16.9 56.425,14.575 U201.14
NetR220_2: R220.2 U202.6 X200.5 | length 22.1
  SIGNAL_1 w0.25: U202.6 36.995,32.905 37.3,32.6 37.3,29.5 38.1,28.7 38.1,17.9 39.13,16.87 X200.5 40.33,16.9 R220.2
NetR221_1: R221.1 U201.17 | length 13.7
  SIGNAL_1 w0.25: R221.1 50.6,14.3 52.275,12.625 U201.17
NetR221_2: R221.2 U203.7 X200.4 | length 9.9
  SIGNAL_1 w0.25: U203.7 36.875,17.875 38.1,16.65 38.1,14.8 38.57,14.33 X200.4 40.33,14.3 R221.2
NetR222_1: R222.1 U201.18 | length 13.2
  SIGNAL_1 w0.25: R222.1 51.9,11.7 52.175,11.975 U201.18
NetR222_2: R222.2 U203.1 X200.3 | length 8
  SIGNAL_1 w0.25: U203.1 37.125,10.255 v1(37.15,10.23) ; X200.3 40.39,11.7 R222.2
  SIGNAL_4 w0.25: v1(37.15,10.23) 38.74,10.23 X200.3
NetR223_1: R223.1 U201.19 | length 13.9
  SIGNAL_1 w0.25: R223.1 50.4,9.2 52.525,11.325 U201.19
NetR223_2: R223.2 U203.2 X200.2 | length 12.1
  SIGNAL_1 w0.25: U203.2 37.125,11.525 v1(37.15,11.5) ; X200.2 40.35,9.2 R223.2
  SIGNAL_4 w0.25: v1(37.15,11.5) 36.05,11.5 35.7,11.15 35.7,9.65 36.1,9.25 X200.2
NetR224_1: R224.1 U201.20 | length 14.7
  SIGNAL_1 w0.25: R224.1 48.9,6.7 52.875,10.675 U201.20
NetR224_2: R224.2 U203.6 X200.1 | length 16.2
  SIGNAL_1 w0.25: U203.6 36.945,16.605 37.3,16.25 37.3,14.45 38.2,13.55 38.2,7.31 38.8,6.71 X200.1 40.31,6.7 R224.2
NetR225_2: R225.2 U201.11 | length 22.7
  SIGNAL_1 w0.25: R225.2 46.65,28.15 52.6,22.2 52.6,20.1 56.175,16.525 U201.11
NetR226_1: R226.1 U201.7 | length 2.7
  SIGNAL_1 w0.25: U201.7 67.825,14.575 R226.1
NetR227_1: R227.1 U202.4 | length 7.3
  SIGNAL_1 w0.25: R227.1 33.4,29.3 34.465,30.365 U202.4
NetR228_1: R228.1 U202.3 | length 6.4
  SIGNAL_1 w0.25: R228.1 34.9,24.75 34.9,25.45 34.2,26.15 34.2,28.7 34.595,29.095 U202.3
NetR229_1: R229.1 U203.4 | length 7.3
  SIGNAL_1 w0.25: R229.1 33.4,13 34.465,14.065 U203.4
NetR230_1: R230.1 U203.3 | length 6.3
  SIGNAL_1 w0.25: R230.1 35.1,8.45 34.85,8.7 34.85,9.147 34.2,9.797 34.2,12.4 34.595,12.795 U203.3
RF_RX: U200.16 W200.1 | length 11.6
  SIGNAL_1 w0.2: U200.16@73.447,37.69 84.99,37.69 W200.1
RX_DATA: U200.8 U201.12 | length 7
  SIGNAL_1 w0.25: U200.8@57.953,19.91 59.39,19.91 59.6,19.7 59.6,16.1 59.375,15.875 U201.12
pads on no net: S201. U200.1 U200.2 U200.3 U200.6 U200.7 U200.9 U200.10 U200.11 U200.12 U200.13 U200.14 U201.9

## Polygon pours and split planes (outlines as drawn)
GND_RX on SIGNAL_2 "02-GND_RX" (solid, remove dead copper, pour order 6): 0,0 100,0 100,50 0,50
3V3_RX on SIGNAL_3 "03-3V3_RX" (solid, remove dead copper, pour order 5): 0,0 100,0 100,50 0,50
GND_RX on SIGNAL_1 "01-GND_RX" (solid, remove dead copper, pour order 7): 0,0 100,0 100,50 0,50
GND_RX on SIGNAL_4 "04-GND_RX" (solid, remove dead copper, pour order 4): 0,0 100,0 100,50 0,50

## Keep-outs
SIGNAL_1:
  region: 99.1,3 ccw(c97,3) 97,5.1 ccw(c97,3) 94.9,3 ccw(c97,3) 97,0.9 ccw(c97,3)
  region: 5.1,3 ccw(c3,3) 3,5.1 ccw(c3,3) 0.9,3 ccw(c3,3) 3,0.9 ccw(c3,3)
  region: 5.1,47 ccw(c3,47) 3,49.1 ccw(c3,47) 0.9,47 ccw(c3,47) 3,44.9 ccw(c3,47)
  region: 99.1,47 ccw(c97,47) 97,49.1 ccw(c97,47) 94.9,47 ccw(c97,47) 97,44.9 ccw(c97,47)
Keep-Out Layer:
  the board outline again, w0.7

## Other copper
SIGNAL_1:
  pour cut-out: 99.1,3 ccw(c97,3) 97,5.1 ccw(c97,3) 94.9,3 ccw(c97,3) 97,0.9 ccw(c97,3)
  pour cut-out: 5.1,3 ccw(c3,3) 3,5.1 ccw(c3,3) 0.9,3 ccw(c3,3) 3,0.9 ccw(c3,3)
  pour cut-out: 5.1,47 ccw(c3,47) 3,49.1 ccw(c3,47) 0.9,47 ccw(c3,47) 3,44.9 ccw(c3,47)
  pour cut-out: 99.1,47 ccw(c97,47) 97,49.1 ccw(c97,47) 94.9,47 ccw(c97,47) 97,44.9 ccw(c97,47)
  text "Rx_433MHz V2.0" at 37.656,46.5 h2
  text "01/04" at 74.286,46.175 h2
  text "Layer 01/04 Top" at 33.324,-23.065 h2
SIGNAL_2:
  text "02/04" at 74.256,46.175 h2
  text "Layer 02/04" at 33.324,-23.065 h2
SIGNAL_3:
  text "03/04" at 74.256,46.175 h2
  text "Layer 03/04" at 33.324,-23.065 h2
SIGNAL_4:
  text "04/04" at 82.364,46.175 h2
  text "Layer 04/04 Bottom" at 69.073,-23.065 h2

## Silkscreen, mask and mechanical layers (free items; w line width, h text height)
Top Overlay:
  drawing of 94 lines, arcs and shapes, not listed
  text "SILKSCREEN TOP" at 66.497,-23.235 h2
DIELECTRIC_1:
  text "SOLDERMASK TOP" at 33.334,-23.005 h2
DIELECTRIC_9:
  text "SOLDERMASK BOTTOM" at 33.344,-23.005 h2
Top Assembly:
  text "U204" at 24.55,41.7 h1 r90
  text "X201" at 15.4,41.25 h1 r90
  text "U202" at 33.45,29.45 h1 r90
  text "U200" at 63.6,28.35 h1
  text "W200" at 90.4,24.65 h1
  text "H200" at 6.6,23.1 h1
  text "X200" at 40.75,13.85 h1 r90
  text "U203" at 33.55,13 h1 r90
  text "U201" at 60,12.95 h1
  text "H201" at 6.6,9.25 h1
  text "Assembly Drawing Top" at 33.604,-23.29 h2
Default User Layer:
  lines w0.025: 1,1 1,49 ; 1,1 85,1 ; 1,1 1,49 ; 1,1 85,1 ; 1,49 85,49 ; 1,49 85,49 ; 85,1 85,49 ; 85,1 85,49
VSCORE_DETAIL:
  lines w0.1: 0,50 100,50
  text "VSCORE DETAIL" at 33.334,-23.005 h2
Panel Dimension:
  circle w0.2: c3,47 r1.1
  circle w0.2: c97,47 r1.1
  circle w0.2: c97,3 r1.1
  circle w0.2: c3,3 r1.1
  lines w0.2: 0,0 0,50 100,50 100,0 0,0
  text "Panel Drawing" at 33.864,-23.295 h2
Single Board Dimensions:
  circle w0.2: c3,3 r1.1
  circle w0.2: c97,3 r1.1
  circle w0.2: c97,47 r1.1
  circle w0.2: c3,47 r1.1
  lines w0.2: 0,0 100,0 100,50 0,50 0,0
  text "Single Board Dimensions" at 33.334,-23.005 h2
TitleBlock_Mirrored:
  drawing of 102 lines, arcs and shapes, not listed
  text "PROJECT:" at 76.049,-13.849 h0.76
  text "TX & RX 433MHZ UT Scintilla Workshop" at 68.987,-15.551 h2
  text "DRAWN BY:" at 76.049,-17.659 h0.76
  text "Lesley Snijder/Henk Mengerink" at 69.191,-19.281 h2
  text "LAYER:" at 76.049,-21.469 h0.76
  text "DATE:" at 16.613,-25.279 h0.76
  text "REV:" at 26.519,-25.279 h0.76
  text "DWG NO:" at 76.049,-25.279 h0.76
  text "30 Apr2021" at 12.549,-27.041 h2
  text "2.0" at 23.217,-27.041 h2
  text "THE INFORMATION HEREIN IS PROPRIETARY TO YOUR DESIGN COMPANY" at 111.709,-27.628 h0.64
TittleBlock:
  drawing of 102 lines, arcs and shapes, not listed
  text "PROJECT:" at 26.889,-13.869 h0.76
  text "TX & RX 433MHZ UT Scintilla Workshop" at 33.747,-15.531 h2
  text "DRAWN BY:" at 26.889,-17.679 h0.76
  text "Lesley Snijder/Henk Mengerink" at 33.747,-19.301 h2
  text "LAYER:" at 26.889,-21.489 h0.76
  text "DWG NO:" at 26.889,-25.299 h0.76
  text "REV:" at 76.419,-25.299 h0.76
  text "DATE:" at 86.325,-25.299 h0.76
  text "2.0" at 79.721,-27.061 h2
  text "30 Apr 2021" at 90.389,-27.061 h2
  text "THE INFORMATION HEREIN IS PROPRIETARY TO YOUR DESIGN COMPANY" at -8.771,-27.648 h0.64
Drill Drawing:
  lines w0.15: -22.95,-45.95 134.55,-45.95 ; -22.95,-39.95 134.55,-39.95 ; -22.95,-62.45 -22.95,-30.95 134.55,-30.95 134.55,-62.45 -22.95,-62.45
  text "E" at 3,96 h2
  text "E" at 97,96 h2
  text "A" at 66.42,91.24 h2
  text "A" at 71.68,91.24 h2
  text "A" at 43.09,90.65 h2
  text "A" at 56.5,90.65 h2
  text "A" at 31,88.55 h2
  text "A" at 6.98,88.49 h2
  text "D" at 43.1,88 h2
  text "D" at 56.5,88 h2
  text "A" at 49.85,87.74 h2
  text "A" at 38.54,86.13 h2
  text "A" at 18.66,85.93 h2
  text "A" at 78.64,85 h2
  text "A" at 82.3,84.67 h2
  text "A" at 41.17,84.05 h2
  text "A" at 54.57,84.05 h2
  text "A" at 83.76,81.72 h2
  text "A" at 78.92,80.83 h2
  text "A" at 58.77,79.72 h2
  text "A" at 51.12,78.4 h2
  text "A" at 54.98,78.4 h2
  text "A" at 65.43,76.73 h2
  text "A" at 70.52,76.73 h2
  text "A" at 73.05,76.73 h2
  text "A" at 6.89,76.65 h2
  text "A" at 83.76,76.64 h2
  text "A" at 51.12,75.85 h2
  text "A" at 54.98,75.85 h2
  text "A" at 68.6,75.09 h2
  text "A" at 30.84,74.25 h2
  text "A" at 56.5,74.18 h2
  text "A" at 51.12,73.3 h2
  text "A" at 79.23,73.15 h2
  text "A" at 83.76,71.56 h2
  text "A" at 51.12,70.8 h2
  text "A" at 79.23,70.6 h2
  text "A" at 65.64,70.55 h2
  text "A" at 68.69,69.57 h2
  text "A" at 54.9,69.55 h2
  text "A" at 18.54,68.46 h2
  text "A" at 57.4,68.46 h2
  text "A" at 65.65,68.25 h2
  text "A" at 51.12,68.2 h2
  text "A" at 69.01,67.28 h2
  text "A" at 83.76,66.48 h2
  text "A" at 69.01,65.96 h2
  text "A" at 51.12,65.7 h2
  text "A" at 70.96,64.65 h2
  text "A" at 79.05,64.65 h2
  text "A" at 69.7,64.39 h2
  text "A" at 51.12,63.15 h2
  text "A" at 6.78,62.23 h2
  text "C" at 60.23,61.67 h2
  text "A" at 83.76,61.4 h2
  text "A" at 51.12,60.6 h2
  text "A" at 64.84,60.6 h2
  text "A" at 30.67,59.95 h2
  text "C" at 60.23,59.13 h2
  text "A" at 64.85,59.1 h2
  text "A" at 78.85,57.44 h2
  text "E" at 3,52 h2
  text "E" at 97,52 h2
  text "E" at 3,46 h2
  text "E" at 97,46 h2
  text "A" at 4.63,41.86 h2
  text "A" at 29.48,41.21 h2
  text "A" at 66.43,40.71 h2
  text "C" at 45.53,40.68 h2
  text "C" at 48.07,40.68 h2
  text "A" at 53.83,40.7 h2
  text "B" at 3.055,38.58 h2
  text "B" at 18.295,38.58 h2
  text "A" at 47.53,38 h2
  text "A" at 34.53,37.67 h2
  text "A" at 50.78,36.1 h2
  text "A" at 46.55,36.06 h2
  text "B" at 3.055,36.04 h2
  text "B" at 18.295,36.04 h2
  text "A" at 46.56,34.91 h2
  text "A" at 77.44,34.69 h2
  text "A" at 82.12,34.69 h2
  text "A" at 50.78,34.2 h2
  text "A" at 74.65,34.16 h2
  text "A" at 34.53,33.87 h2
  text "B" at 3.055,33.5 h2
  text "B" at 18.295,33.5 h2
  text "A" at 39.37,32.92 h2
  text "A" at 42.26,32.6 h2
  text "A" at 50.79,31.77 h2
  text "A" at 83.11,31.62 h2
  text "A" at 39.37,31.02 h2
  text "B" at 3.055,30.96 h2
  text "B" at 18.295,30.96 h2
  text "A" at 51.5,29.2 h2
  text "A" at 78.52,28.46 h2
  text "B" at 3.055,28.42 h2
  text "B" at 18.295,28.42 h2
  text "A" at 37.98,28.32 h2
  text "A" at 26.55,26.7 h2
  text "A" at 83.11,26.54 h2
  text "A" at 30.1,26.47 h2
  text "A" at 51.5,26.21 h2
  text "A" at 25.5,26 h2
  text "A" at 14.55,24.94 h2
  text "C" at 42,23.78 h2
  text "A" at 30.78,23.09 h2
  text "A" at 37.97,23.1 h2
  text "A" at 51.12,22.25 h2
  text "B" at 2.905,21.78 h2
  text "B" at 18.145,21.78 h2
  text "A" at 83.11,21.46 h2
  text "C" at 42,21.24 h2
  text "A" at 34.53,19.89 h2
  text "B" at 2.905,19.24 h2
  text "B" at 18.145,19.24 h2
  text "C" at 42,18.7 h2
  text "A" at 48.38,18.56 h2
  text "B" at 2.905,16.7 h2
  text "B" at 18.145,16.7 h2
  text "A" at 48.38,16.66 h2
  text "A" at 83.11,16.38 h2
  text "C" at 42,16.16 h2
  text "A" at 34.53,16.08 h2
  text "A" at 63.03,15.82 h2
  text "A" at 39.39,15.15 h2
  text "A" at 60.27,14.54 h2
  text "B" at 2.905,14.16 h2
  text "B" at 18.145,14.16 h2
  text "A" at 78.41,14.04 h2
  text "A" at 66.43,13.85 h2
  text "C" at 42,13.62 h2
  text "A" at 39.37,13.24 h2
  text "A" at 60.24,12.92 h2
  text "A" at 49.35,12.9 h2
  text "A" at 51.85,11.73 h2
  text "B" at 2.905,11.62 h2
  text "B" at 18.145,11.62 h2
  text "A" at 63.25,11.59 h2
  text "A" at 83.11,11.3 h2
  text "C" at 42,11.08 h2
  text "A" at 63.39,10.63 h2
  text "A" at 39.19,9.84 h2
  text "A" at 63.39,9.31 h2
  text "A" at 66.49,8.88 h2
  text "A" at 58.79,8.73 h2
  text "A" at 26,8.7 h2
  text "A" at 30.05,8.7 h2
  text "C" at 42,8.54 h2
  text "A" at 37.1,7.14 h2
  text "A" at 52.5,6.8 h2
  text "D" at 55.15,6.8 h2
  text "A" at 13.66,6.75 h2
  text "C" at 42,6 h2
  text "A" at 30.94,5.5 h2
  text "E" at 3,2 h2
  text "E" at 97,2 h2
  text "Through Holes" at 47.75,-34.7 h1.5
  text "All Drills (unless specified) +/- 0.1000 (MM)" at 25.675,-37.7 h1.5
  text "Symbol" at -19.208,-43.7 h1.5
  text "Diameter" at 1.834,-43.7 h1.5
  text "Tolerance" at 29.561,-43.7 h1.5
  text "Plated" at 52.798,-43.7 h1.5
  text "HoleName" at 85.805,-43.7 h1.5
  text "Quantity" at 120.337,-43.7 h1.5
  text "A" at -15.45,-48.2 h1.5
  text "0.3000" at 3.379,-48.2 h1.5
  text "+/- 0.1000" at 29.132,-48.2 h1.5
  text "Yes" at 55.01,-48.2 h1.5
  text "Rnd 0.30 +/-Tol 0.10" at 77.714,-48.2 h1.5
  text "114" at 124.046,-48.2 h1.5
  text "B" at -15.45,-51.2 h1.5
  text "0.9000" at 3.379,-51.2 h1.5
  text "+/- 0.1000" at 29.132,-51.2 h1.5
  text "Yes" at 55.01,-51.2 h1.5
  text "Rnd 0.90 +/-Tol 0.10" at 77.714,-51.2 h1.5
  text "20" at 124.766,-51.2 h1.5
  text "C" at -15.45,-54.2 h1.5
  text "1.0000" at 3.402,-54.2 h1.5
  text "+/- 0.1000" at 29.132,-54.2 h1.5
  text "Yes" at 55.01,-54.2 h1.5
  text "Rnd 1.00 +/-Tol 0.10" at 77.74,-54.2 h1.5
  text "12" at 124.78,-54.2 h1.5
  text "D" at -15.45,-57.2 h1.5
  text "0.8500" at 3.385,-57.2 h1.5
  text "+/- 0.1000" at 29.132,-57.2 h1.5
  text "No" at 55.767,-57.2 h1.5
  text "Rnd 0.85 +/-Tol 0.10 Non-Plated" at 69.797,-57.2 h1.5
  text "3" at 125.55,-57.2 h1.5
  text "E" at -15.45,-60.2 h1.5
  text "2.2000" at 3.379,-60.2 h1.5
  text "+/- 0.1000" at 29.132,-60.2 h1.5
  text "No" at 55.767,-60.2 h1.5
  text "Rnd 2.20 +/-Tol 0.10 Non-Plated" at 69.79,-60.2 h1.5
  text "8" at 125.55,-60.2 h1.5

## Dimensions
0,50 to 3,1.9 on Single Board Dimensions
0,0 to 1.9,3 on Single Board Dimensions
0,0 to 0,50 on Single Board Dimensions
0,50 to 1.9,47 on Single Board Dimensions
3,3 to 5.6,4.3 on Single Board Dimensions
